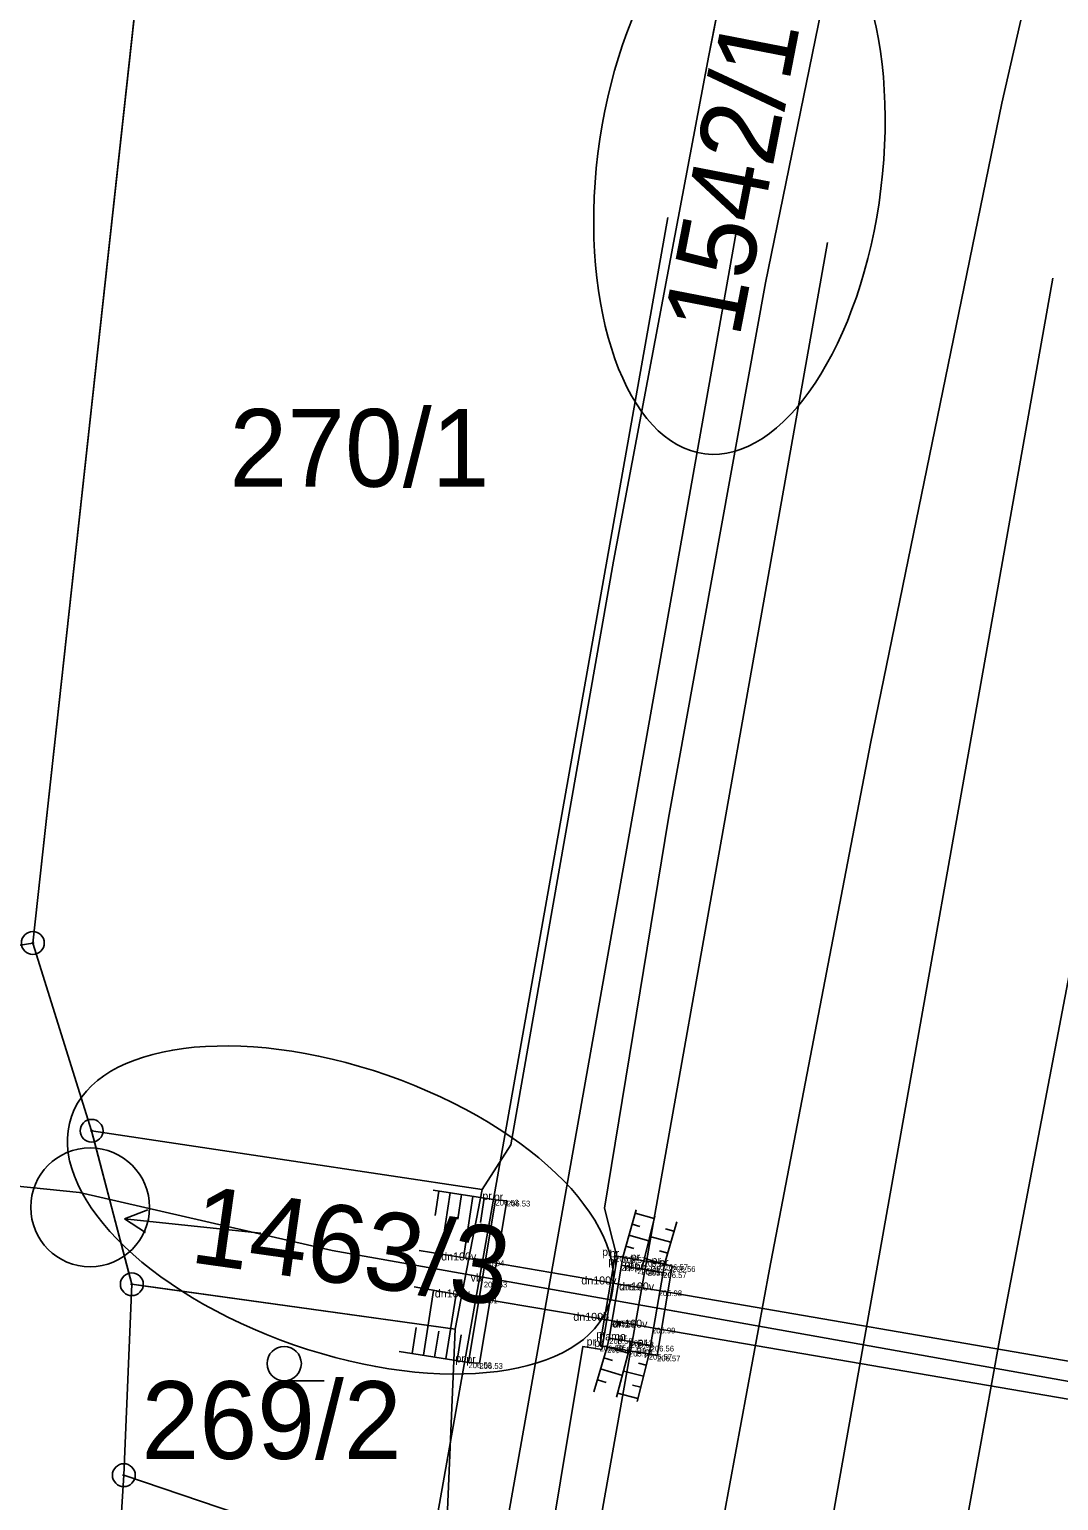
# Model space of a CAD drawing. Extents: x -537341 to -532984, y -1143469 to -1141314.
# Drawn here: x -534589.9 to -534544.9, y -1142958.1 to -1142893.8 of the extents above; entities that cross this region are included whole.
import ezdxf

# ---------------------------------------------------------------- set-up
doc = ezdxf.new("R2010")
doc.units = 0
for name, color, linetype in [('Hranice parcel', 7, 'Continuous'), ('parcelní_č_2000', 7, 'Continuous'), ('u_II_etapa', 7, 'Continuous'), ('U_KM', 7, 'Continuous'), ('u_obec_Horní_Moš', 7, 'Continuous'), ('u_osa_toku', 7, 'Continuous'), ('u_pricne', 7, 'Continuous'), ('U_SOUKROMÉ', 7, 'Continuous'), ('u_SŽDC', 7, 'Continuous'), ('u_ŘSD', 7, 'Continuous'), ('Vnitřní kresba', 7, 'Continuous'), ('Značky bodu BP', 7, 'Continuous'), ('Značky kultur', 7, 'Continuous'), ('ˇ1', 7, 'Continuous'), ('ˇ12', 7, 'Continuous'), ('ˇ13', 7, 'Continuous'), ('ˇ18', 7, 'Continuous'), ('ˇ3', 7, 'Continuous'), ('ˇ8', 7, 'Continuous'), ('ˇ9', 7, 'Continuous')]:
    doc.layers.add(name, color=color, linetype=linetype)

msp = doc.modelspace()

# ---------------------------------------------------------------- linework, layer by layer
at = {"layer": 'Hranice parcel'}
for p, q in [((-534587.17, -1142941.94), (-534570.08, -1142944.51)), ((-534585.41, -1142948.65), (-534587.17, -1142941.94)), ((-534571.26, -1142950.61), (-534570.08, -1142944.51)), ((-534585.76, -1142957), (-534585.41, -1142948.65)), ((-534571.26, -1142950.61), (-534585.41, -1142948.65)), ((-534571.73, -1142961.74), (-534571.26, -1142950.61)), ((-534586.25, -1142964.92), (-534585.76, -1142957)), ((-534585.76, -1142957), (-534571.73, -1142961.74))]:
    msp.add_line(p, q, dxfattribs=at)
for points in [[(-534531.1, -1142789.76), (-534533.47, -1142799.68), (-534540.49, -1142829.02), (-534548.41, -1142861.98), (-534552.45, -1142879.68), (-534553.59, -1142884.83), (-534557.69, -1142904.87), (-534561.93, -1142928.27), (-534564.73, -1142945.32), (-534564.18, -1142947.49), (-534564.85, -1142951.5), (-534565.68, -1142951.38), (-534567.63, -1142963.12), (-534568.99, -1142970.64), (-534571.93, -1142984.8), (-534572.36, -1142984.68)], [(-534587.17, -1142941.94), (-534589.74, -1142933.73), (-534583.95, -1142880.85)], [(-534570.08, -1142944.51), (-534568.83, -1142942.56), (-534564.34, -1142917.04), (-534560.16, -1142894.92), (-534558.08, -1142884.24)]]:
    msp.add_lwpolyline(points, dxfattribs=at)
at = {"layer": 'u_II_etapa'}
for centre, major_axis in [((-534558.825, -1142899.974), (-1.516, -12.366)), ((-534576.283, -1142945.404), (-11.768, 4.091))]:
    msp.add_ellipse(centre, major_axis=major_axis, ratio=0.50074, dxfattribs=at)
at = {"layer": 'U_KM'}
msp.add_circle((-534587.234, -1142945.287), 2.6, dxfattribs=at)
at = {"layer": 'u_obec_Horní_Moš'}
for p, q in [((-534570.08, -1142944.51), (-534587.17, -1142941.94)), ((-534570.08, -1142944.51), (-534571.26, -1142950.61)), ((-534571.26, -1142950.61), (-534570.08, -1142944.51)), ((-534585.537, -1142948.166), (-534585.41, -1142948.65)), ((-534585.41, -1142948.65), (-534584.915, -1142948.719)), ((-534584.915, -1142948.719), (-534571.26, -1142950.61)), ((-534571.26, -1142950.61), (-534571.73, -1142961.74)), ((-534565.68, -1142951.38), (-534564.85, -1142951.5))]:
    msp.add_line(p, q, dxfattribs=at)
for points in [[(-534558.08, -1142884.24), (-534560.16, -1142894.92), (-534564.34, -1142917.04), (-534568.83, -1142942.56), (-534570.08, -1142944.51)], [(-534561.93, -1142928.27), (-534557.69, -1142904.87), (-534553.59, -1142884.83)], [(-534564.85, -1142951.5), (-534564.18, -1142947.49), (-534564.73, -1142945.32), (-534561.93, -1142928.27)], [(-534587.17, -1142941.94), (-534587.043, -1142942.424), (-534585.537, -1142948.166)], [(-534572.36, -1142984.68), (-534571.93, -1142984.8), (-534568.99, -1142970.64), (-534567.63, -1142963.12), (-534565.68, -1142951.38)]]:
    msp.add_lwpolyline(points, dxfattribs=at)
at = {"layer": 'u_osa_toku'}
msp.add_lwpolyline([(-534623.017, -1142940.808), (-534607.282, -1142942.643), (-534587.693, -1142944.646), (-534576.649, -1142947.17), (-534561.658, -1142949.835), (-534540.722, -1142953.556), (-534529.931, -1142954.371), (-534502.381, -1142950.31), (-534495.908, -1142949.498), (-534484.457, -1142953.581), (-534476.389, -1142957.2)], dxfattribs=at)
at = {"layer": 'u_pricne'}
for p, q in [((-534581.309, -1143010.915), (-534561.951, -1142902.008)), ((-534558.94, -1142902.482), (-534578.3, -1143011.402)), ((-534554.973, -1142903.106), (-534574.336, -1143012.043)), ((-534545.116, -1142904.657), (-534564.487, -1143013.636))]:
    msp.add_line(p, q, dxfattribs=at)
at = {"layer": 'U_SOUKROMÉ'}
for p, q in [((-534583.95, -1142880.85), (-534589.74, -1142933.73)), ((-534560.16, -1142894.92), (-534558.08, -1142884.24)), ((-534564.34, -1142917.04), (-534560.16, -1142894.92)), ((-534589.74, -1142933.73), (-534587.17, -1142941.94)), ((-534587.17, -1142941.94), (-534570.08, -1142944.51)), ((-534585.41, -1142948.65), (-534585.76, -1142957)), ((-534584.915, -1142948.719), (-534585.41, -1142948.65)), ((-534571.26, -1142950.61), (-534584.915, -1142948.719)), ((-534571.73, -1142961.74), (-534571.26, -1142950.61)), ((-534585.76, -1142957), (-534571.73, -1142961.74))]:
    msp.add_line(p, q, dxfattribs=at)
msp.add_lwpolyline([(-534570.08, -1142944.51), (-534568.83, -1142942.56), (-534564.34, -1142917.04)], dxfattribs=at)
msp.add_circle((-534578.743, -1142952.12), 0.75, dxfattribs=at)
msp.add_circle((-534578.743, -1142952.12), 0.75, dxfattribs=at)
at = {"layer": 'u_SŽDC'}
for p, q in [((-534589.74, -1142933.73), (-534583.95, -1142880.85)), ((-534616.87, -1142938.09), (-534589.74, -1142933.73)), ((-534589.74, -1142933.73), (-534616.87, -1142938.09)), ((-534616.87, -1142938.09), (-534589.74, -1142933.73)), ((-534587.17, -1142941.94), (-534589.74, -1142933.73)), ((-534585.76, -1142957), (-534585.41, -1142948.65)), ((-534586.25, -1142964.92), (-534585.76, -1142957))]:
    msp.add_line(p, q, dxfattribs=at)
msp.add_lwpolyline([(-534585.41, -1142948.65), (-534585.537, -1142948.166), (-534587.043, -1142942.424), (-534587.17, -1142941.94)], dxfattribs=at)
at = {"layer": 'u_ŘSD'}
for p, q in [((-534539.18, -1142861.24), (-534547.35, -1142897.01)), ((-534547.35, -1142897.01), (-534539.18, -1142861.24)), ((-534547.35, -1142897.01), (-534553.09, -1142925.01)), ((-534553.09, -1142925.01), (-534547.35, -1142897.01)), ((-534547.45, -1142951.09), (-534542.43, -1142924.78)), ((-534542.43, -1142924.78), (-534547.45, -1142951.09)), ((-534553.09, -1142925.01), (-534557.51, -1142947.99)), ((-534557.51, -1142947.99), (-534553.09, -1142925.01)), ((-534557.51, -1142947.99), (-534559.49, -1142958.72)), ((-534559.49, -1142958.72), (-534557.51, -1142947.99)), ((-534550.33, -1142967.04), (-534547.45, -1142951.09)), ((-534547.45, -1142951.09), (-534550.33, -1142967.04))]:
    msp.add_line(p, q, dxfattribs=at)
msp.add_lwpolyline([(-534531.1, -1142789.76), (-534533.47, -1142799.68), (-534540.49, -1142829.02), (-534548.41, -1142861.98), (-534552.45, -1142879.68), (-534553.59, -1142884.83), (-534557.69, -1142904.87), (-534561.93, -1142928.27), (-534564.73, -1142945.32), (-534564.18, -1142947.49), (-534564.85, -1142951.5), (-534565.68, -1142951.38), (-534567.63, -1142963.12), (-534568.99, -1142970.64), (-534571.93, -1142984.8), (-534572.36, -1142984.68)], dxfattribs=at)
at = {"layer": 'Vnitřní kresba'}
for p, q in [((-534547.35, -1142897.01), (-534539.18, -1142861.24)), ((-534553.09, -1142925.01), (-534547.35, -1142897.01)), ((-534547.45, -1142951.09), (-534542.43, -1142924.78)), ((-534557.51, -1142947.99), (-534553.09, -1142925.01)), ((-534559.49, -1142958.72), (-534557.51, -1142947.99)), ((-534550.33, -1142967.04), (-534547.45, -1142951.09))]:
    msp.add_line(p, q, dxfattribs=at)
at = {"layer": 'Značky bodu BP'}
for centre, radius in [((-534589.74, -1142933.73), 0.5), ((-534589.74, -1142933.73), 0.0303), ((-534587.17, -1142941.94), 0.5), ((-534587.17, -1142941.94), 0.0303), ((-534585.41, -1142948.65), 0.5), ((-534585.41, -1142948.65), 0.0303), ((-534585.76, -1142957), 0.5), ((-534585.76, -1142957), 0.0303)]:
    msp.add_circle(centre, radius, dxfattribs=at)
at = {"layer": 'Značky kultur'}
for p, q in [((-534585.73, -1142945.786), (-534584.706, -1142945.39)), ((-534579.763, -1142946.413), (-534585.73, -1142945.786)), ((-534585.73, -1142945.786), (-534584.81, -1142946.387)), ((-534578.743, -1142952.87), (-534576.993, -1142952.87))]:
    msp.add_line(p, q, dxfattribs=at)
msp.add_circle((-534578.743, -1142952.12), 0.75, dxfattribs=at)
at = {"layer": 'ˇ1'}
for p, q in [((-534569.5, -1142944.96), (-534569.5, -1142944.96)), ((-534569.5, -1142944.96), (-534569.5, -1142944.96)), ((-534569, -1142945), (-534569, -1142945)), ((-534569, -1142945), (-534569, -1142945)), ((-534570.14, -1142947.61), (-534570.14, -1142947.61)), ((-534570.14, -1142947.61), (-534570.14, -1142947.61)), ((-534564.26, -1142947.41), (-534564.26, -1142947.41)), ((-534564.26, -1142947.41), (-534564.26, -1142947.41)), ((-534563.99, -1142947.81), (-534563.99, -1142947.81)), ((-534563.99, -1142947.81), (-534563.99, -1142947.81)), ((-534563.93, -1142947.47), (-534563.93, -1142947.47)), ((-534563.93, -1142947.47), (-534563.93, -1142947.47)), ((-534563.29, -1142947.96), (-534563.29, -1142947.96)), ((-534563.29, -1142947.96), (-534563.29, -1142947.96)), ((-534563.12, -1142947.98), (-534563.12, -1142947.98)), ((-534563.12, -1142947.98), (-534563.12, -1142947.98)), ((-534563.01, -1142947.63), (-534563.01, -1142947.63)), ((-534563.01, -1142947.63), (-534563.01, -1142947.63)), ((-534562.1, -1142947.78), (-534562.1, -1142947.78)), ((-534562.1, -1142947.78), (-534562.1, -1142947.78)), ((-534561.77, -1142947.86), (-534561.77, -1142947.86)), ((-534561.77, -1142947.86), (-534561.77, -1142947.86)), ((-534570.01, -1142948.54), (-534570.01, -1142948.54)), ((-534570.01, -1142948.54), (-534570.01, -1142948.54)), ((-534562.84, -1142948.03), (-534562.84, -1142948.03)), ((-534562.84, -1142948.03), (-534562.84, -1142948.03)), ((-534562.16, -1142948.13), (-534562.16, -1142948.13)), ((-534562.16, -1142948.13), (-534562.16, -1142948.13)), ((-534570.42, -1142949.23), (-534570.42, -1142949.23)), ((-534570.42, -1142949.23), (-534570.42, -1142949.23)), ((-534564.01, -1142948.66), (-534564.01, -1142948.66)), ((-534564.01, -1142948.66), (-534564.01, -1142948.66)), ((-534562.36, -1142948.92), (-534562.36, -1142948.92)), ((-534562.36, -1142948.92), (-534562.36, -1142948.92)), ((-534564.45, -1142950.24), (-534564.45, -1142950.24)), ((-534564.45, -1142950.24), (-534564.45, -1142950.24)), ((-534564.36, -1142950.25), (-534564.36, -1142950.25)), ((-534564.36, -1142950.25), (-534564.36, -1142950.25)), ((-534562.65, -1142950.55), (-534562.65, -1142950.55)), ((-534562.65, -1142950.55), (-534562.65, -1142950.55)), ((-534564.52, -1142951.01), (-534564.52, -1142951.01)), ((-534564.52, -1142951.01), (-534564.52, -1142951.01)), ((-534563.63, -1142951.1), (-534563.63, -1142951.1)), ((-534563.63, -1142951.1), (-534563.63, -1142951.1)), ((-534563.59, -1142951.17), (-534563.59, -1142951.17)), ((-534563.59, -1142951.17), (-534563.59, -1142951.17)), ((-534564.94, -1142951.33), (-534564.94, -1142951.33)), ((-534564.94, -1142951.33), (-534564.94, -1142951.33)), ((-534564.61, -1142951.39), (-534564.61, -1142951.39)), ((-534564.61, -1142951.39), (-534564.61, -1142951.39)), ((-534563.66, -1142951.56), (-534563.66, -1142951.56)), ((-534563.66, -1142951.56), (-534563.66, -1142951.56)), ((-534562.79, -1142951.7), (-534562.79, -1142951.7)), ((-534562.79, -1142951.7), (-534562.79, -1142951.7)), ((-534562.71, -1142951.34), (-534562.71, -1142951.34)), ((-534562.71, -1142951.34), (-534562.71, -1142951.34)), ((-534562.43, -1142951.77), (-534562.43, -1142951.77)), ((-534562.43, -1142951.77), (-534562.43, -1142951.77)), ((-534570.68, -1142952.07), (-534570.68, -1142952.07)), ((-534570.68, -1142952.07), (-534570.68, -1142952.07)), ((-534570.2, -1142952.1), (-534570.2, -1142952.1)), ((-534570.2, -1142952.1), (-534570.2, -1142952.1))]:
    msp.add_line(p, q, dxfattribs=at)
at = {"layer": 'ˇ12'}
for p, q in [((-534569.5, -1142944.96), (-534572.23, -1142944.54)), ((-534563.93, -1142947.47), (-534563.35, -1142945.4)), ((-534563.01, -1142947.63), (-534562.53, -1142945.68)), ((-534562.1, -1142947.78), (-534561.57, -1142945.92)), ((-534570.14, -1142947.61), (-534572.84, -1142947.18)), ((-534563.12, -1142947.98), (-534563.01, -1142947.63)), ((-534570.42, -1142949.23), (-534573.06, -1142948.77)), ((-534564.01, -1142948.66), (-534562.36, -1142948.92)), ((-534564.36, -1142950.25), (-534562.65, -1142950.55)), ((-534563.66, -1142951.56), (-534563.59, -1142951.16)), ((-534570.68, -1142952.07), (-534573.71, -1142951.59)), ((-534564.61, -1142951.39), (-534565.2, -1142953.35)), ((-534563.66, -1142951.56), (-534564.2, -1142953.59)), ((-534562.78, -1142951.7), (-534563.3, -1142953.78))]:
    msp.add_line(p, q, dxfattribs=at)
at = {"layer": 'ˇ13'}
for p, q in [((-534571.971, -1142944.58), (-534572.135, -1142945.649)), ((-534571.477, -1142944.656), (-534571.889, -1142947.332)), ((-534570.983, -1142944.732), (-534571.147, -1142945.803)), ((-534570.488, -1142944.808), (-534570.901, -1142947.489)), ((-534569.994, -1142944.884), (-534570.159, -1142945.957)), ((-534563.525, -1142946.026), (-534563.185, -1142946.121)), ((-534563.39, -1142945.544), (-534562.554, -1142945.779)), ((-534563.66, -1142946.507), (-534562.793, -1142946.75)), ((-534561.826, -1142946.818), (-534562.746, -1142946.556)), ((-534561.689, -1142946.337), (-534562.064, -1142946.231)), ((-534563.795, -1142946.989), (-534563.442, -1142947.087)), ((-534561.963, -1142947.299), (-534562.324, -1142947.196)), ((-534562.1, -1142947.78), (-534562.985, -1142947.528)), ((-534572.655, -1142951.757), (-534572.206, -1142948.919)), ((-534571.668, -1142951.914), (-534571.22, -1142949.091)), ((-534573.149, -1142951.679), (-534572.969, -1142950.541)), ((-534572.162, -1142951.835), (-534571.982, -1142950.703)), ((-534571.174, -1142951.992), (-534570.996, -1142950.866)), ((-534564.61, -1142951.39), (-534563.689, -1142951.667)), ((-534564.898, -1142952.348), (-534563.946, -1142952.634)), ((-534564.754, -1142951.869), (-534564.379, -1142951.982)), ((-534563.023, -1142952.67), (-534563.897, -1142952.452)), ((-534562.901, -1142952.185), (-534563.248, -1142952.098)), ((-534565.042, -1142952.826), (-534564.655, -1142952.943)), ((-534563.144, -1142953.155), (-534563.497, -1142953.067)), ((-534563.265, -1142953.64), (-534564.154, -1142953.418))]:
    msp.add_line(p, q, dxfattribs=at)
at = {"layer": 'ˇ8'}
for p, q in [((-534570.14, -1142947.61), (-534564.01, -1142948.66)), ((-534564.36, -1142950.25), (-534570.42, -1142949.23)), ((-534562.36, -1142948.92), (-534542.37, -1142952.37)), ((-534542.73, -1142953.97), (-534562.65, -1142950.55))]:
    msp.add_line(p, q, dxfattribs=at)
at = {"layer": 'ˇ9'}
for p, q in [((-534569.5, -1142944.96), (-534570.68, -1142952.07)), ((-534570.2, -1142952.1), (-534569, -1142945)), ((-534569, -1142945), (-534569.5, -1142944.96)), ((-534564.94, -1142951.33), (-534564.26, -1142947.41)), ((-534563.99, -1142947.81), (-534564.52, -1142951.01)), ((-534564.26, -1142947.41), (-534563.93, -1142947.47)), ((-534563.93, -1142947.47), (-534563.99, -1142947.81)), ((-534563.29, -1142947.96), (-534563.99, -1142947.81)), ((-534563.93, -1142947.47), (-534563.01, -1142947.63)), ((-534563.12, -1142947.98), (-534563.29, -1142947.96)), ((-534562.84, -1142948.03), (-534563.12, -1142947.98)), ((-534563.01, -1142947.63), (-534562.1, -1142947.78)), ((-534561.77, -1142947.86), (-534562.43, -1142951.77)), ((-534562.1, -1142947.78), (-534562.16, -1142948.13)), ((-534562.1, -1142947.78), (-534561.77, -1142947.86)), ((-534562.16, -1142948.13), (-534562.84, -1142948.03)), ((-534562.71, -1142951.34), (-534562.16, -1142948.13)), ((-534564.52, -1142951.01), (-534564.61, -1142951.39)), ((-534564.52, -1142951.01), (-534563.59, -1142951.16)), ((-534563.59, -1142951.16), (-534562.71, -1142951.34)), ((-534564.61, -1142951.39), (-534564.94, -1142951.33)), ((-534563.66, -1142951.56), (-534564.61, -1142951.39)), ((-534562.78, -1142951.7), (-534563.66, -1142951.56)), ((-534562.71, -1142951.34), (-534562.78, -1142951.7)), ((-534562.43, -1142951.77), (-534562.78, -1142951.7)), ((-534570.68, -1142952.07), (-534570.2, -1142952.1))]:
    msp.add_line(p, q, dxfattribs=at)

# ---------------------------------------------------------------- texts
at = {"layer": 'parcelní_č_2000'}
for s, rotation, p in [('1542/1', 79, (-534558.833, -1142907.319)), ('1463/3', 352, (-534582.921, -1142947.681))]:
    msp.add_text(s, height=3.4, rotation=rotation, dxfattribs=at).set_placement(p)
for s, p in [('270/1', (-534581.138, -1142913.78)), ('269/2', (-534584.983, -1142956.29))]:
    msp.add_text(s, height=3.4, dxfattribs=at).set_placement(p)
at = {"layer": 'ˇ18'}
for s, p in [('pr', (-534570.073, -1142944.96)), ('pr', (-534569.573, -1142945)), ('dn100v', (-534571.873, -1142947.61)), ('pr', (-534564.833, -1142947.41)), ('pr', (-534564.503, -1142947.47)), ('pr', (-534564.563, -1142947.81)), ('pr', (-534563.863, -1142947.96)), ('pr', (-534563.693, -1142947.98)), ('pr', (-534563.583, -1142947.63)), ('pr', (-534563.413, -1142948.03)), ('pr', (-534562.733, -1142948.13)), ('pr', (-534562.673, -1142947.78)), ('pr', (-534562.343, -1142947.86)), ('vb', (-534570.586, -1142948.54)), ('dn100v', (-534565.743, -1142948.66)), ('dn100v', (-534564.093, -1142948.92)), ('dn100v', (-534572.153, -1142949.23)), ('dn100v', (-534566.093, -1142950.25)), ('vb', (-534565.026, -1142950.24)), ('dn100v', (-534564.383, -1142950.55)), ('pr', (-534565.513, -1142951.33)), ('pr', (-534565.183, -1142951.39)), ('pr', (-534565.093, -1142951.01)), ('pamo', (-534564.961, -1142951.1)), ('pr', (-534564.163, -1142951.16)), ('pr', (-534563.283, -1142951.34)), ('pr', (-534571.253, -1142952.07)), ('pr', (-534570.773, -1142952.1)), ('pr', (-534564.233, -1142951.56)), ('pr', (-534563.353, -1142951.7)), ('pr', (-534563.003, -1142951.77))]:
    msp.add_text(s, height=0.35, dxfattribs=at).set_placement(p)
at = {"layer": 'ˇ3'}
for s, p in [('206.53 ', (-534569.5, -1142945.21)), ('206.53 ', (-534569, -1142945.25)), ('206.04 ', (-534570.14, -1142947.86)), ('206.57 ', (-534564.26, -1142947.66)), ('206.57 ', (-534563.99, -1142948.06)), ('206.57 ', (-534563.93, -1142947.72)), ('205.57 ', (-534563.29, -1142948.21)), ('205.52 ', (-534563.12, -1142948.23)), ('205.54 ', (-534563.01, -1142947.88)), ('206.57 ', (-534562.1, -1142948.03)), ('206.56 ', (-534561.77, -1142948.11)), ('206.53 ', (-534570.01, -1142948.79)), ('205.57 ', (-534562.84, -1142948.28)), ('206.57 ', (-534562.16, -1142948.38)), ('206.01 ', (-534570.42, -1142949.48)), ('205.99 ', (-534564.01, -1142948.91)), ('205.98 ', (-534562.36, -1142949.17)), ('206.56 ', (-534564.45, -1142950.49)), ('205.98 ', (-534564.36, -1142950.5)), ('205.99 ', (-534562.65, -1142950.8)), ('206.58 ', (-534564.52, -1142951.26)), ('205.13 ', (-534563.63, -1142951.35)), ('205.53 ', (-534563.59, -1142951.42)), ('206.59 ', (-534564.94, -1142951.58)), ('206.58 ', (-534564.61, -1142951.64)), ('205.54 ', (-534563.66, -1142951.81)), ('206.57 ', (-534562.79, -1142951.95)), ('206.56 ', (-534562.71, -1142951.59)), ('206.57 ', (-534562.43, -1142952.02)), ('206.53 ', (-534570.68, -1142952.32)), ('206.53 ', (-534570.2, -1142952.35))]:
    msp.add_text(s, height=0.25, dxfattribs=at).set_placement(p)

doc.saveas('drawing.dxf')
